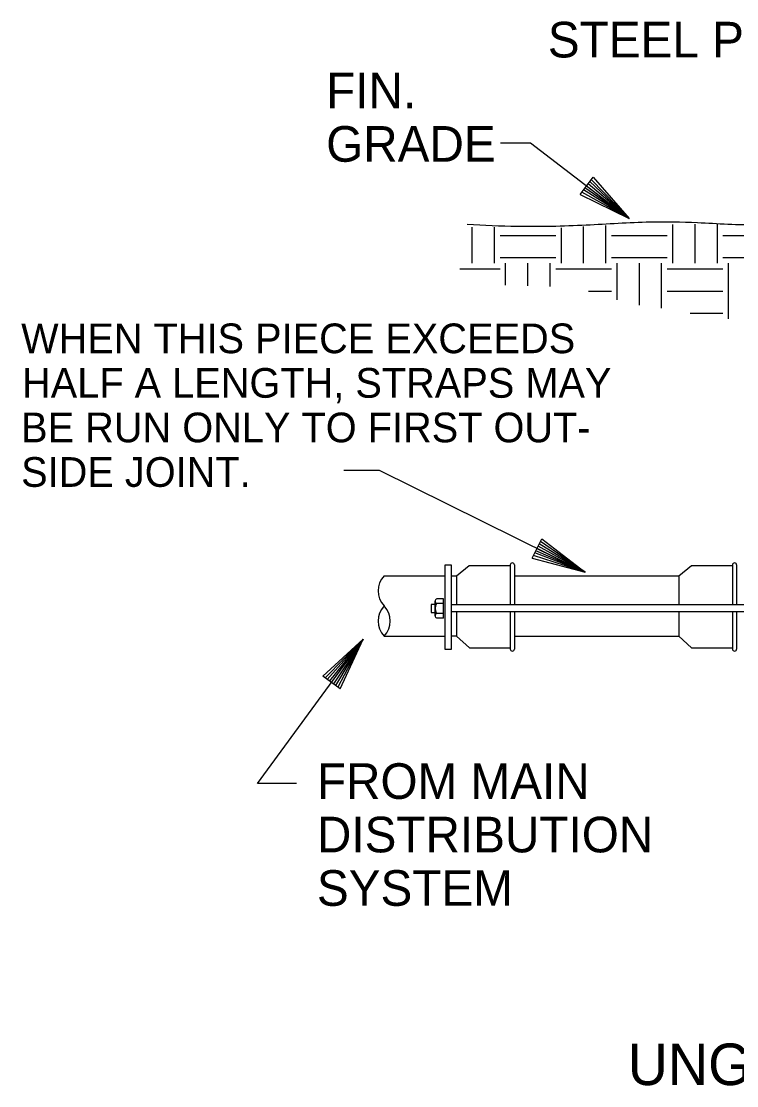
# Model space of a CAD drawing. Extents: x 10040.55 to 10045.84, y 10033.26 to 10035.76.
# Drawn here: x 10041.6917 to 10041.8924, y 10035.3007 to 10035.5994 of the extents above; entities that cross this region are included whole.
import ezdxf

# ---------------------------------------------------------------- set-up
doc = ezdxf.new("R2010")
doc.units = 0
doc.layers.add('Level 2', color=7, linetype='Continuous')

msp = doc.modelspace()

# ---------------------------------------------------------------- linework, layer by layer
at = {"layer": 'Level 2'}
for p, q in [((10041.84847, 10035.55085), (10041.85215, 10035.55564)), ((10041.86224, 10035.54407), (10041.85119, 10035.55442)), ((10041.86224, 10035.54407), (10041.85164, 10035.55499)), ((10041.85215, 10035.55564), (10041.86224, 10035.54407)), ((10041.86224, 10035.54407), (10041.84894, 10035.55147)), ((10041.86224, 10035.54407), (10041.84943, 10035.55215)), ((10041.86224, 10035.54407), (10041.84985, 10035.55267)), ((10041.85027, 10035.55323), (10041.86224, 10035.54407)), ((10041.86224, 10035.54407), (10041.85074, 10035.55382)), ((10041.84847, 10035.55085), (10041.86224, 10035.54407)), ((10041.85574, 10035.53152), (10041.85574, 10035.54213)), ((10041.87449, 10035.53152), (10041.87449, 10035.54243)), ((10041.88074, 10035.53152), (10041.88074, 10035.54245)), ((10041.88699, 10035.53152), (10041.88699, 10035.54255)), ((10041.81824, 10035.53152), (10041.81824, 10035.54166)), ((10041.82449, 10035.53152), (10041.82449, 10035.54166)), ((10041.82605, 10035.53933), (10041.84168, 10035.53933)), ((10041.84324, 10035.53152), (10041.84324, 10035.54149)), ((10041.84949, 10035.53152), (10041.84949, 10035.54181)), ((10041.8573, 10035.53933), (10041.87293, 10035.53933)), ((10041.88855, 10035.53933), (10041.90418, 10035.53933)), ((10041.82605, 10035.53308), (10041.84168, 10035.53308)), ((10041.8573, 10035.53308), (10041.87293, 10035.53308)), ((10041.88855, 10035.53308), (10041.90418, 10035.53308)), ((10041.82761, 10035.5254), (10041.82761, 10035.53152)), ((10041.83386, 10035.52521), (10041.83386, 10035.53152)), ((10041.84011, 10035.52501), (10041.84011, 10035.53152)), ((10041.85886, 10035.52125), (10041.85886, 10035.53152)), ((10041.86511, 10035.51978), (10041.86511, 10035.53152)), ((10041.87136, 10035.51893), (10041.87136, 10035.53152)), ((10041.89011, 10035.5159), (10041.89011, 10035.53152)), ((10041.81477, 10035.52996), (10041.82605, 10035.52996)), ((10041.84168, 10035.52996), (10041.8573, 10035.52996)), ((10041.87293, 10035.52996), (10041.88855, 10035.52996)), ((10041.85089, 10035.52371), (10041.8573, 10035.52371)), ((10041.87293, 10035.52371), (10041.88855, 10035.52371)), ((10041.87939, 10035.51746), (10041.88855, 10035.51746)), ((10041.83506, 10035.4488), (10041.83775, 10035.4542)), ((10041.84989, 10035.4448), (10041.83704, 10035.45282)), ((10041.84989, 10035.4448), (10041.83738, 10035.45346)), ((10041.83775, 10035.4542), (10041.84989, 10035.4448)), ((10041.84989, 10035.4448), (10041.83541, 10035.44949)), ((10041.84989, 10035.4448), (10041.83576, 10035.45025)), ((10041.84989, 10035.4448), (10041.83607, 10035.45084)), ((10041.83638, 10035.45148), (10041.84989, 10035.4448)), ((10041.84989, 10035.4448), (10041.83672, 10035.45215)), ((10041.81741, 10035.44661), (10041.81381, 10035.44371)), ((10041.82889, 10035.44661), (10041.81741, 10035.44661)), ((10041.82889, 10035.44684), (10041.82889, 10035.43566)), ((10041.83006, 10035.44684), (10041.83006, 10035.43566)), ((10041.83506, 10035.4488), (10041.84989, 10035.4448)), ((10041.87974, 10035.44661), (10041.87615, 10035.44371)), ((10041.89122, 10035.44661), (10041.87974, 10035.44661)), ((10041.89122, 10035.44684), (10041.89122, 10035.43574)), ((10041.8924, 10035.44684), (10041.8924, 10035.43574)), ((10041.81057, 10035.44371), (10041.79354, 10035.44371)), ((10041.81381, 10035.44371), (10041.81247, 10035.44371)), ((10041.81381, 10035.44371), (10041.81381, 10035.43573)), ((10041.87618, 10035.44371), (10041.8301, 10035.44371)), ((10041.87615, 10035.44371), (10041.87615, 10035.43573)), ((10041.80783, 10035.43259), (10041.80783, 10035.4367)), ((10041.81017, 10035.43602), (10041.80826, 10035.43602)), ((10041.81017, 10035.43739), (10041.80827, 10035.43739)), ((10041.81017, 10035.43191), (10041.81017, 10035.43739)), ((10041.81246, 10035.43574), (10041.98621, 10035.43574)), ((10041.81017, 10035.43327), (10041.80826, 10035.43327)), ((10041.81017, 10035.43191), (10041.80826, 10035.43191)), ((10041.98621, 10035.43365), (10041.81256, 10035.43365)), ((10041.81381, 10035.43365), (10041.81381, 10035.42683)), ((10041.82889, 10035.43373), (10041.82889, 10035.42325)), ((10041.83006, 10035.43373), (10041.83006, 10035.42325)), ((10041.87615, 10035.43365), (10041.87615, 10035.42683)), ((10041.89122, 10035.43365), (10041.89122, 10035.42325)), ((10041.8924, 10035.43365), (10041.8924, 10035.42325)), ((10041.77634, 10035.41568), (10041.78767, 10035.42603)), ((10041.78767, 10035.42603), (10041.777, 10035.41519)), ((10041.78767, 10035.42603), (10041.77757, 10035.41475)), ((10041.78767, 10035.42603), (10041.77818, 10035.41431)), ((10041.77878, 10035.41386), (10041.78767, 10035.42603)), ((10041.78767, 10035.42603), (10041.77935, 10035.41346)), ((10041.78767, 10035.42603), (10041.77989, 10035.41304)), ((10041.78767, 10035.42603), (10041.78058, 10035.41256)), ((10041.7812, 10035.4121), (10041.78767, 10035.42603)), ((10041.79354, 10035.4269), (10041.81057, 10035.4269)), ((10041.81381, 10035.42689), (10041.81247, 10035.42689)), ((10041.81381, 10035.42689), (10041.81745, 10035.42361)), ((10041.83013, 10035.4269), (10041.87618, 10035.4269)), ((10041.87615, 10035.42689), (10041.87978, 10035.42361)), ((10041.81745, 10035.42361), (10041.82889, 10035.42361)), ((10041.87978, 10035.42361), (10041.89122, 10035.42361)), ((10041.7812, 10035.4121), (10041.77634, 10035.41568))]:
    msp.add_line(p, q, dxfattribs=at)
for points in [[(10041.82619, 10035.5653), (10041.83458, 10035.5653), (10041.86224, 10035.54407)], [(10041.78223, 10035.47345), (10041.7921, 10035.47345), (10041.84989, 10035.4448)], [(10041.80782, 10035.43578), (10041.80668, 10035.43578), (10041.80668, 10035.43352), (10041.80782, 10035.43352)], [(10041.7689, 10035.38554), (10041.75803, 10035.38554), (10041.78767, 10035.42603)]]:
    msp.add_lwpolyline(points, dxfattribs=at)
msp.add_lwpolyline([(10041.81057, 10035.44679), (10041.81057, 10035.42324), (10041.81246, 10035.42324), (10041.81246, 10035.44679)], close=True, dxfattribs=at)
for centre, radius, start, end in [((10041.82947, 10035.44684), 0.000589, 0, 180), ((10041.89181, 10035.44684), 0.000589, 0, 180), ((10041.79791, 10035.43956), 0.00607, 135.9788, 224.0225), ((10041.79791, 10035.43112), 0.00607, 135.9775, 224.0212), ((10041.78917, 10035.43112), 0.00607, 315.9788, 44.0225), ((10041.81037, 10035.43464), 0.00253, 147.0062, 212.943), ((10041.80861, 10035.4367), 0.000766, 116.7827, 241.8391), ((10041.80861, 10035.43259), 0.000766, 117.8877, 242.0342), ((10041.82947, 10035.42325), 0.000589, 180, 0), ((10041.89181, 10035.42325), 0.000589, 180, 0)]:
    msp.add_arc(centre, radius, start, end, dxfattribs=at)
msp.add_spline([(10041.90693, 10035.54303), (10041.89848, 10035.54234), (10041.8814, 10035.54285), (10041.8681, 10035.54303), (10041.85016, 10035.54217), (10041.83083, 10035.54182), (10041.81685, 10035.54234)], degree=3, dxfattribs=at)

# ---------------------------------------------------------------- texts
for s, height, p in [('STEEL PIPE', 0.01, (10041.83944, 10035.58926)), ('FIN. ', 0.01, (10041.77726, 10035.575)), ('GRADE', 0.01, (10041.77726, 10035.56)), ('WHEN THIS PIECE EXCEEDS', 0.0083333, (10041.6917, 10035.50627)), ('HALF A LENGTH, STRAPS MAY', 0.0083333, (10041.69195, 10035.49377)), ('BE RUN ONLY TO FIRST OUT-', 0.0083333, (10041.6917, 10035.48127)), ('SIDE JOINT.', 0.0083333, (10041.6917, 10035.46877)), ('FROM MAIN ', 0.01, (10041.77467, 10035.3812)), ('DISTRIBUTION', 0.01, (10041.77467, 10035.3662)), ('SYSTEM', 0.01, (10041.77467, 10035.3512)), ('UNGROUTED PIPE', 0.0116667, (10041.86186, 10035.30089))]:
    msp.add_text(s, height=height, dxfattribs=at).set_placement(p)

doc.saveas('drawing.dxf')
